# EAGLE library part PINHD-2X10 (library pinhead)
PIN HEADER
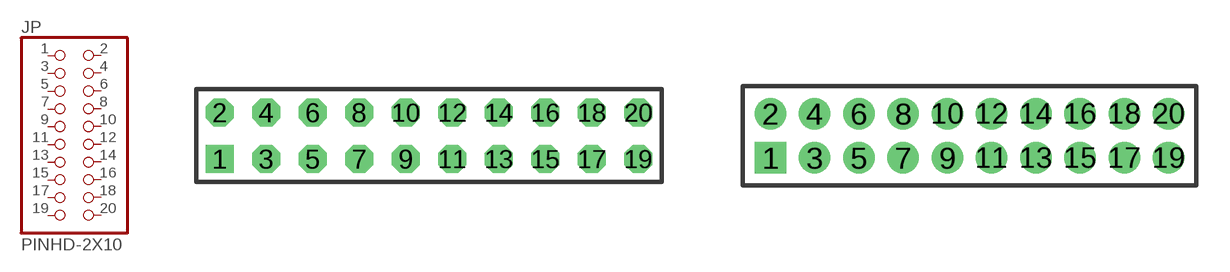
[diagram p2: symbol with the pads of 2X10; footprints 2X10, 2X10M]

Designator prefix JP

## PINHD-2X10  [2X10]
1  1  pas
2  2  pas
3  3  pas
4  4  pas
5  5  pas
6  6  pas
7  7  pas
8  8  pas
9  9  pas
10  10  pas
11  11  pas
12  12  pas
13  13  pas
14  14  pas
15  15  pas
16  16  pas
17  17  pas
18  18  pas
19  19  pas
20  20  pas

## PINHD-2X10M  [2X10M]
Pads as for 2X10

## Footprint 2X10 (pad centres in mm)
PIN HEADER - 0.1"
drill 1.016 square: 1 -11.43,-1.27
drill 1.016 octagon: 2 -11.43,1.27; 3 -8.89,-1.27; 4 -8.89,1.27; 5 -6.35,-1.27; 6 -6.35,1.27; 7 -3.81,-1.27; 8 -3.81,1.27; 9 -1.27,-1.27; 10 -1.27,1.27; 11 1.27,-1.27; 12 1.27,1.27; 13 3.81,-1.27; 14 3.81,1.27; 15 6.35,-1.27; 16 6.35,1.27; 17 8.89,-1.27; 18 8.89,1.27; 19 11.43,-1.27; 20 11.43,1.27

## Footprint 2X10M (pad centres in mm)
PIN HEADER - 2MM"
drill 0.914 square: 1 -9,-1
drill 0.914 round: 2 -9,1; 3 -7,-1; 4 -7,1; 5 -5,-1; 6 -5,1; 7 -3,-1; 8 -3,1; 9 -1,-1; 10 -1,1; 11 1,-1; 12 1,1; 13 3,-1; 14 3,1; 15 5,-1; 16 5,1; 17 7,-1; 18 7,1; 19 9,-1; 20 9,1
